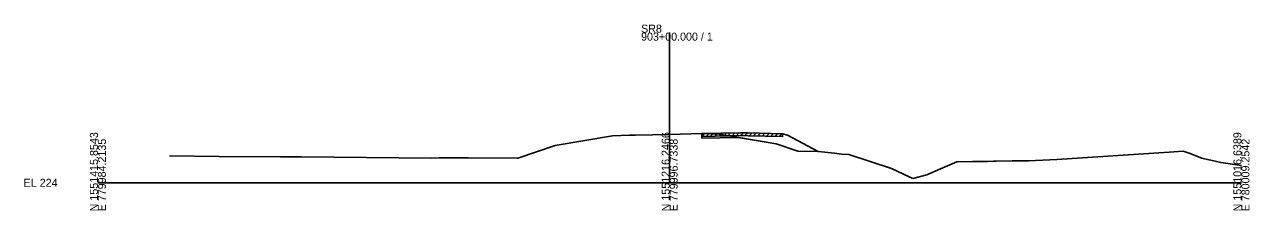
# Model space of a CAD drawing. Extents: x -26 to 787523, y -10 to 1545496.
# Drawn here: x -25.7 to 402.8, y 7990.3 to 8055.3 of the extents above; entities that cross this region are included whole.
import ezdxf

# ---------------------------------------------------------------- set-up
doc = ezdxf.new("R2010")
doc.units = 0
for name, color, linetype in [('50', 7, 'Continuous'), ('XS_CELL', 7, 'Continuous'), ('XS_M_SHAPES_EARTHWORK', 7, 'Continuous'), ('XS_P_FINISHED_GRADE', 7, 'Continuous'), ('XS_P_SUBGRADE_GRANULAR', 7, 'Continuous'), ('XS_X_GROUND', 7, 'Continuous')]:
    doc.layers.add(name, color=color, linetype=linetype)

msp = doc.modelspace()

# ---------------------------------------------------------------- linework, layer by layer
at = {"layer": '50'}
for p, q in [((211.29, 8016.2), (212.31, 8017.22)), ((211.29, 8016.2), (211.29, 8017.2)), ((211.29, 8016.2), (224.83, 8016.48)), ((212.79, 8016.23), (213.81, 8017.25)), ((214.29, 8016.26), (215.32, 8017.29)), ((215.8, 8016.3), (216.82, 8017.32)), ((217.3, 8016.33), (218.33, 8017.35)), ((218.81, 8016.36), (219.83, 8017.38)), ((220.31, 8016.39), (221.33, 8017.41)), ((221.81, 8016.42), (222.84, 8017.44)), ((223.32, 8016.45), (224.34, 8017.47)), ((224.82, 8016.48), (225.84, 8017.5)), ((224.83, 8016.48), (225.68, 8016.5)), ((225.68, 8016.5), (227.45, 8016.46)), ((226.33, 8016.49), (227.3, 8017.46)), ((227.45, 8016.46), (239.5, 8016.17)), ((227.83, 8016.45), (228.81, 8017.43)), ((229.33, 8016.41), (230.31, 8017.39)), ((230.84, 8016.38), (231.82, 8017.36)), ((232.34, 8016.34), (233.32, 8017.32)), ((233.85, 8016.31), (234.82, 8017.28)), ((235.35, 8016.27), (236.33, 8017.25)), ((236.85, 8016.24), (237.83, 8017.21)), ((238.36, 8016.2), (239.34, 8017.18)), ((239.5, 8017.17), (239.5, 8016.17))]:
    msp.add_line(p, q, dxfattribs=at)
at = {"layer": 'XS_CELL'}
for p, q in [((200, 8000), (200, 8052.5)), ((0, 8000), (200, 8000)), ((200, 8000), (400, 8000))]:
    msp.add_line(p, q, dxfattribs=at)
at = {"layer": 'XS_M_SHAPES_EARTHWORK'}
for points in [[(224.83, 8016.48), (225.68, 8016.5), (227.45, 8016.46), (239.5, 8016.17), (239.5, 8017.17), (227.45, 8017.46), (225.68, 8017.5), (224.83, 8017.48), (211.29, 8017.2), (217.29, 8016.96), (220.67, 8016.4)], [(239.5, 8017.17), (239.5, 8016.17), (227.45, 8016.46), (225.68, 8016.5), (224.83, 8016.48), (220.67, 8016.4), (217.29, 8016.96), (211.29, 8017.2), (224.83, 8017.48), (225.68, 8017.5), (227.45, 8017.46)], [(211.29, 8016.2), (211.29, 8017.2), (217.29, 8016.96), (220.67, 8016.4)], [(211.29, 8016.2), (211.29, 8017.2), (217.29, 8016.96), (220.67, 8016.4)], [(211.29, 8015.6), (211.29, 8016.2), (220.67, 8016.4), (223.92, 8015.86)], [(211.29, 8015.6), (211.29, 8016.2), (220.67, 8016.4), (223.92, 8015.86)], [(224.83, 8016.48), (225.68, 8016.5), (227.45, 8016.46), (239.5, 8016.17), (239.5, 8017.17), (241.24, 8016.65), (251.96, 8010.96), (244.85, 8011.1), (237.26, 8013.63), (223.92, 8015.86), (220.67, 8016.4)], [(239.5, 8017.17), (239.5, 8016.17), (227.45, 8016.46), (225.68, 8016.5), (224.83, 8016.48), (220.67, 8016.4), (223.92, 8015.86), (237.26, 8013.63), (244.85, 8011.1), (251.96, 8010.96), (241.24, 8016.65)]]:
    msp.add_lwpolyline(points, close=True, dxfattribs=at)
at = {"layer": 'XS_P_FINISHED_GRADE'}
for p, q in [((211.29, 8017.2), (217.29, 8016.96)), ((217.29, 8016.96), (237.26, 8013.63)), ((237.26, 8013.63), (244.85, 8011.1)), ((251.96, 8010.96), (244.85, 8011.1))]:
    msp.add_line(p, q, dxfattribs=at)
at = {"layer": 'XS_P_SUBGRADE_GRANULAR'}
for p, q in [((211.29, 8017.2), (211.29, 8015.6)), ((211.29, 8015.6), (223.92, 8015.86))]:
    msp.add_line(p, q, dxfattribs=at)
at = {"layer": 'XS_X_GROUND'}
for p, q in [((160, 8013.02), (180, 8016.36)), ((180, 8016.36), (186, 8016.6)), ((186, 8016.6), (188, 8016.64)), ((188, 8016.64), (200, 8016.88)), ((200, 8016.88), (211.29, 8017.2)), ((211.29, 8017.2), (224.83, 8017.48)), ((224.83, 8017.48), (225.68, 8017.5)), ((225.68, 8017.5), (227.45, 8017.46)), ((227.45, 8017.46), (239.5, 8017.17)), ((239.5, 8017.17), (241.24, 8016.65)), ((241.24, 8016.65), (251.96, 8010.96)), ((25.07, 8009.37), (42.36, 8009.24)), ((146.91, 8008.66), (160, 8013.02)), ((251.96, 8010.96), (257.69, 8010.3)), ((257.69, 8010.3), (260.14, 8010.01)), ((260.14, 8010.01), (262.71, 8009.87)), ((262.71, 8009.87), (277.57, 8005.02)), ((335.42, 8008.19), (374.71, 8010.66)), ((374.71, 8010.66), (379.67, 8011.04)), ((379.67, 8011.04), (381.69, 8010.34)), ((381.69, 8010.34), (386.2, 8008.64)), ((42.36, 8009.24), (63.89, 8009.08)), ((63.89, 8009.08), (67.33, 8009.05)), ((67.33, 8009.05), (70.18, 8009.03)), ((70.18, 8009.03), (71.24, 8009.02)), ((71.24, 8009.02), (116.57, 8008.66)), ((116.57, 8008.66), (119.24, 8008.68)), ((119.24, 8008.68), (122.61, 8008.69)), ((122.61, 8008.69), (129.56, 8008.69)), ((129.56, 8008.69), (146.62, 8008.65)), ((146.62, 8008.65), (146.91, 8008.66)), ((277.57, 8005.02), (281.78, 8003.03)), ((294.8, 8004.88), (300.43, 8007.34)), ((300.43, 8007.34), (305.98, 8007.41)), ((305.98, 8007.41), (311.15, 8007.47)), ((311.15, 8007.47), (313.24, 8007.5)), ((313.24, 8007.5), (314.37, 8007.51)), ((314.37, 8007.51), (319.79, 8007.62)), ((319.79, 8007.62), (320.85, 8007.63)), ((320.85, 8007.63), (325.54, 8007.68)), ((325.54, 8007.68), (335.42, 8008.19)), ((386.2, 8008.64), (388.56, 8008.02)), ((388.56, 8008.02), (389.29, 8007.9)), ((389.29, 8007.9), (392.82, 8007.06)), ((392.82, 8007.06), (400, 8006.07)), ((281.78, 8003.03), (285.1, 8001.45)), ((285.1, 8001.45), (289.96, 8002.76)), ((289.96, 8002.76), (294.8, 8004.88))]:
    msp.add_line(p, q, dxfattribs=at)

# ---------------------------------------------------------------- texts
at = {"layer": 'XS_CELL'}
for s, p in [('SR8', (190, 8052.5)), ('903+00.000 / 1', (190, 8049.7)), ('EL 224', (-26, 7998.6))]:
    msp.add_text(s, height=2.8, dxfattribs=at).set_placement(p)
for s, p in [('N 1551415.8543', (0, 7990)), ('E 779984.2135', (2.8, 7990)), ('N 1551216.2466', (200, 7990)), ('E 779996.7338', (202.8, 7990)), ('N 1551016.6389', (400, 7990)), ('E 780009.2542', (402.8, 7990))]:
    msp.add_text(s, height=2.8, rotation=90, dxfattribs=at).set_placement(p)

doc.saveas('drawing.dxf')
